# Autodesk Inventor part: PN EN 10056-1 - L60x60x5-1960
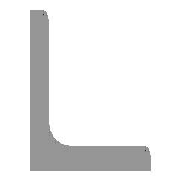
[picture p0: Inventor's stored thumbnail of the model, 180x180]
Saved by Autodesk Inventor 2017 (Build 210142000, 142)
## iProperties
IsCustomPart: 1
_CCFamilyMember: 130
_CCFamilyDisplayName: PN EN 10056-1 (Kątownik równoramienny) - Kątownik równoramienny
_FrameMemberDoc: Frame Member File
_Version: 15.0.0
_GetPNFromCC: 1
Created: 2016-02
Part Number: PN EN 10056-1 - L60x60x5-1960
Material: Stal, miękka
Description: Kątownik równoramienny
Document SubType Name: Modeling
Standard: PN
Designer: X
Standards Organization: PN
Language: pl-PL
Size Designation: L60x60x5
Categories: <MemberInstance><Categories><Category DisplayName="Kształtowniki konstrukcyjne" InternalName="089c4875-fa83-4c05-b084-43b9cc11f5ed" Mnemonic="GRDR"><CategoryPar
Stock Number: L60x60x5
Density: 7.85 g/cm^3
Appearance: Częściowo polerowana
Mass: 8952.61 g
Surface Area: 4581.04 cm^2
Volume: 1140.46 cm^3
G_W: 60,000 mm
G_H: 60,000 mm
G_L: 1960,000 mm
Author: X
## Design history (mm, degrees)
node "Płaszczyzna początkowa"
node "Płaszczyzna końcowa"
sketch "Szkic"
  geometry: L1 (-11.517, -3.517)-(-11.517, 39.483); L2 (-16.517, 43.483)-(-15.517, 43.483); L3 (-16.517, -16.517)-(-16.517, 43.483); L4 (-16.517, -16.517)-(43.483, -16.517); L5 (43.483, -15.517)-(43.483, -16.517); L6 (-3.517, -11.517)-(39.483, -11.517); L7 (0, 56.477)-(0, -28.683) reference; L8 (-28.683, 0)-(56.477, 0) reference; A1 r 8 centre (-3.517, -3.517) between (-11.517, -3.517) and (-3.517, -11.517); A2 r 4 centre (-15.517, 39.483) between (-11.517, 39.483) and (-15.517, 43.483); A3 r 4 centre (39.483, -15.517) between (43.483, -15.517) and (39.483, -11.517); 3 further points
  constraints: 12 end point, 6 point on circle, 6 point on line, 6 tangent, 3 centre point, 3 horizontal, 3 vertical, 1 equal radius
  dimensions: "d4" = 60 distance of L3.start L4.end (= b); "d6" = 60 distance of L3.start L2.start (= b); "d8" = 5 distance of point (43.483, -11.517) L4.end (= ParT); "d10" = 5 distance of L2.start point (-11.517, 43.483) (= ParT); "d17" = 8 radius of A1 (= R); "d18" = 4 radius of A2 (= R1); "d19" = 16.51748 distance between parallel lines of L8 L4 (= ex); "d20" = 16.51748 distance between parallel lines of L3 L7 (= d19)
extrude "Bryła" new body sketch "Szkic" stored distance "d11" = 1960 (= G_L); taper "d12" = 0 deg
node "Driven Length"
  sketch "Sketch3"
    geometry: L1 (0, 0)-(10, 0) reference
    constraints: 2 end point, 1 horizontal
  workplane "Work Plane10"
  sketch "Sketch4"
    geometry: L1 (-2, 0)-(12, 0) reference; L2 (-2, 1960)-(12, 1960) reference
    dimensions: "d24" = 1960 distance between parallel lines of L1 L2 (derived)
body "Solid1"
other parameters: "b" = 60 [user parameter; used in 3 equation terms], "ParT" = 5 [user parameter; used in 3 equation terms], "R" = 8 [user parameter; used in 1 equation term], "R1" = 4 [user parameter; used in 1 equation term], "G_L" = 1960 (= d24) [user parameter; used in 1 equation term], "d7" = 4 (derived), "d9" = 4 (derived), "ex" = 16.51748 (computed from b, ParT) [user parameter; used in 1 equation term], "G_OFFSET_START" = 0 [user parameter; used in 1 equation term], "G_OFFSET_END" = 0 [user parameter; used in 1 equation term], "d21" = 0 (computed from G_OFFSET_START), "d23" = 90 deg
